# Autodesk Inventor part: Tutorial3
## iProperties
Shininess: 64.0
Length Units: 11269
Angle Units: 11279
Time Units: 11290
Mass Units: 11283
Length Display Precision: 3
Angle Display Precision: 2
Compacted: True
Part Number: Tutorial3
Document SubType Name: Modeling
Created: 2002-12
Designer: deepak
Density: 0.0
Volumn: 0.0
Area: 0.0
PropertySet Name: Model Information
Control State: 0
Master: False
Checked Out: False
Author: deepak
